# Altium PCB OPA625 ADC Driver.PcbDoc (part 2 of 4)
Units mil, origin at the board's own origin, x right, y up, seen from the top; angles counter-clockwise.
Board outline 4590 x 3930 mil, 4 copper layers (Layer 1 - Top Layer, Layer 2 - GND, Layer 3 - PWR, Layer 4 - Bottom Layer), stack 59.034 mil thick; 428 components, 236 nets, 1203 pads, 546 vias.
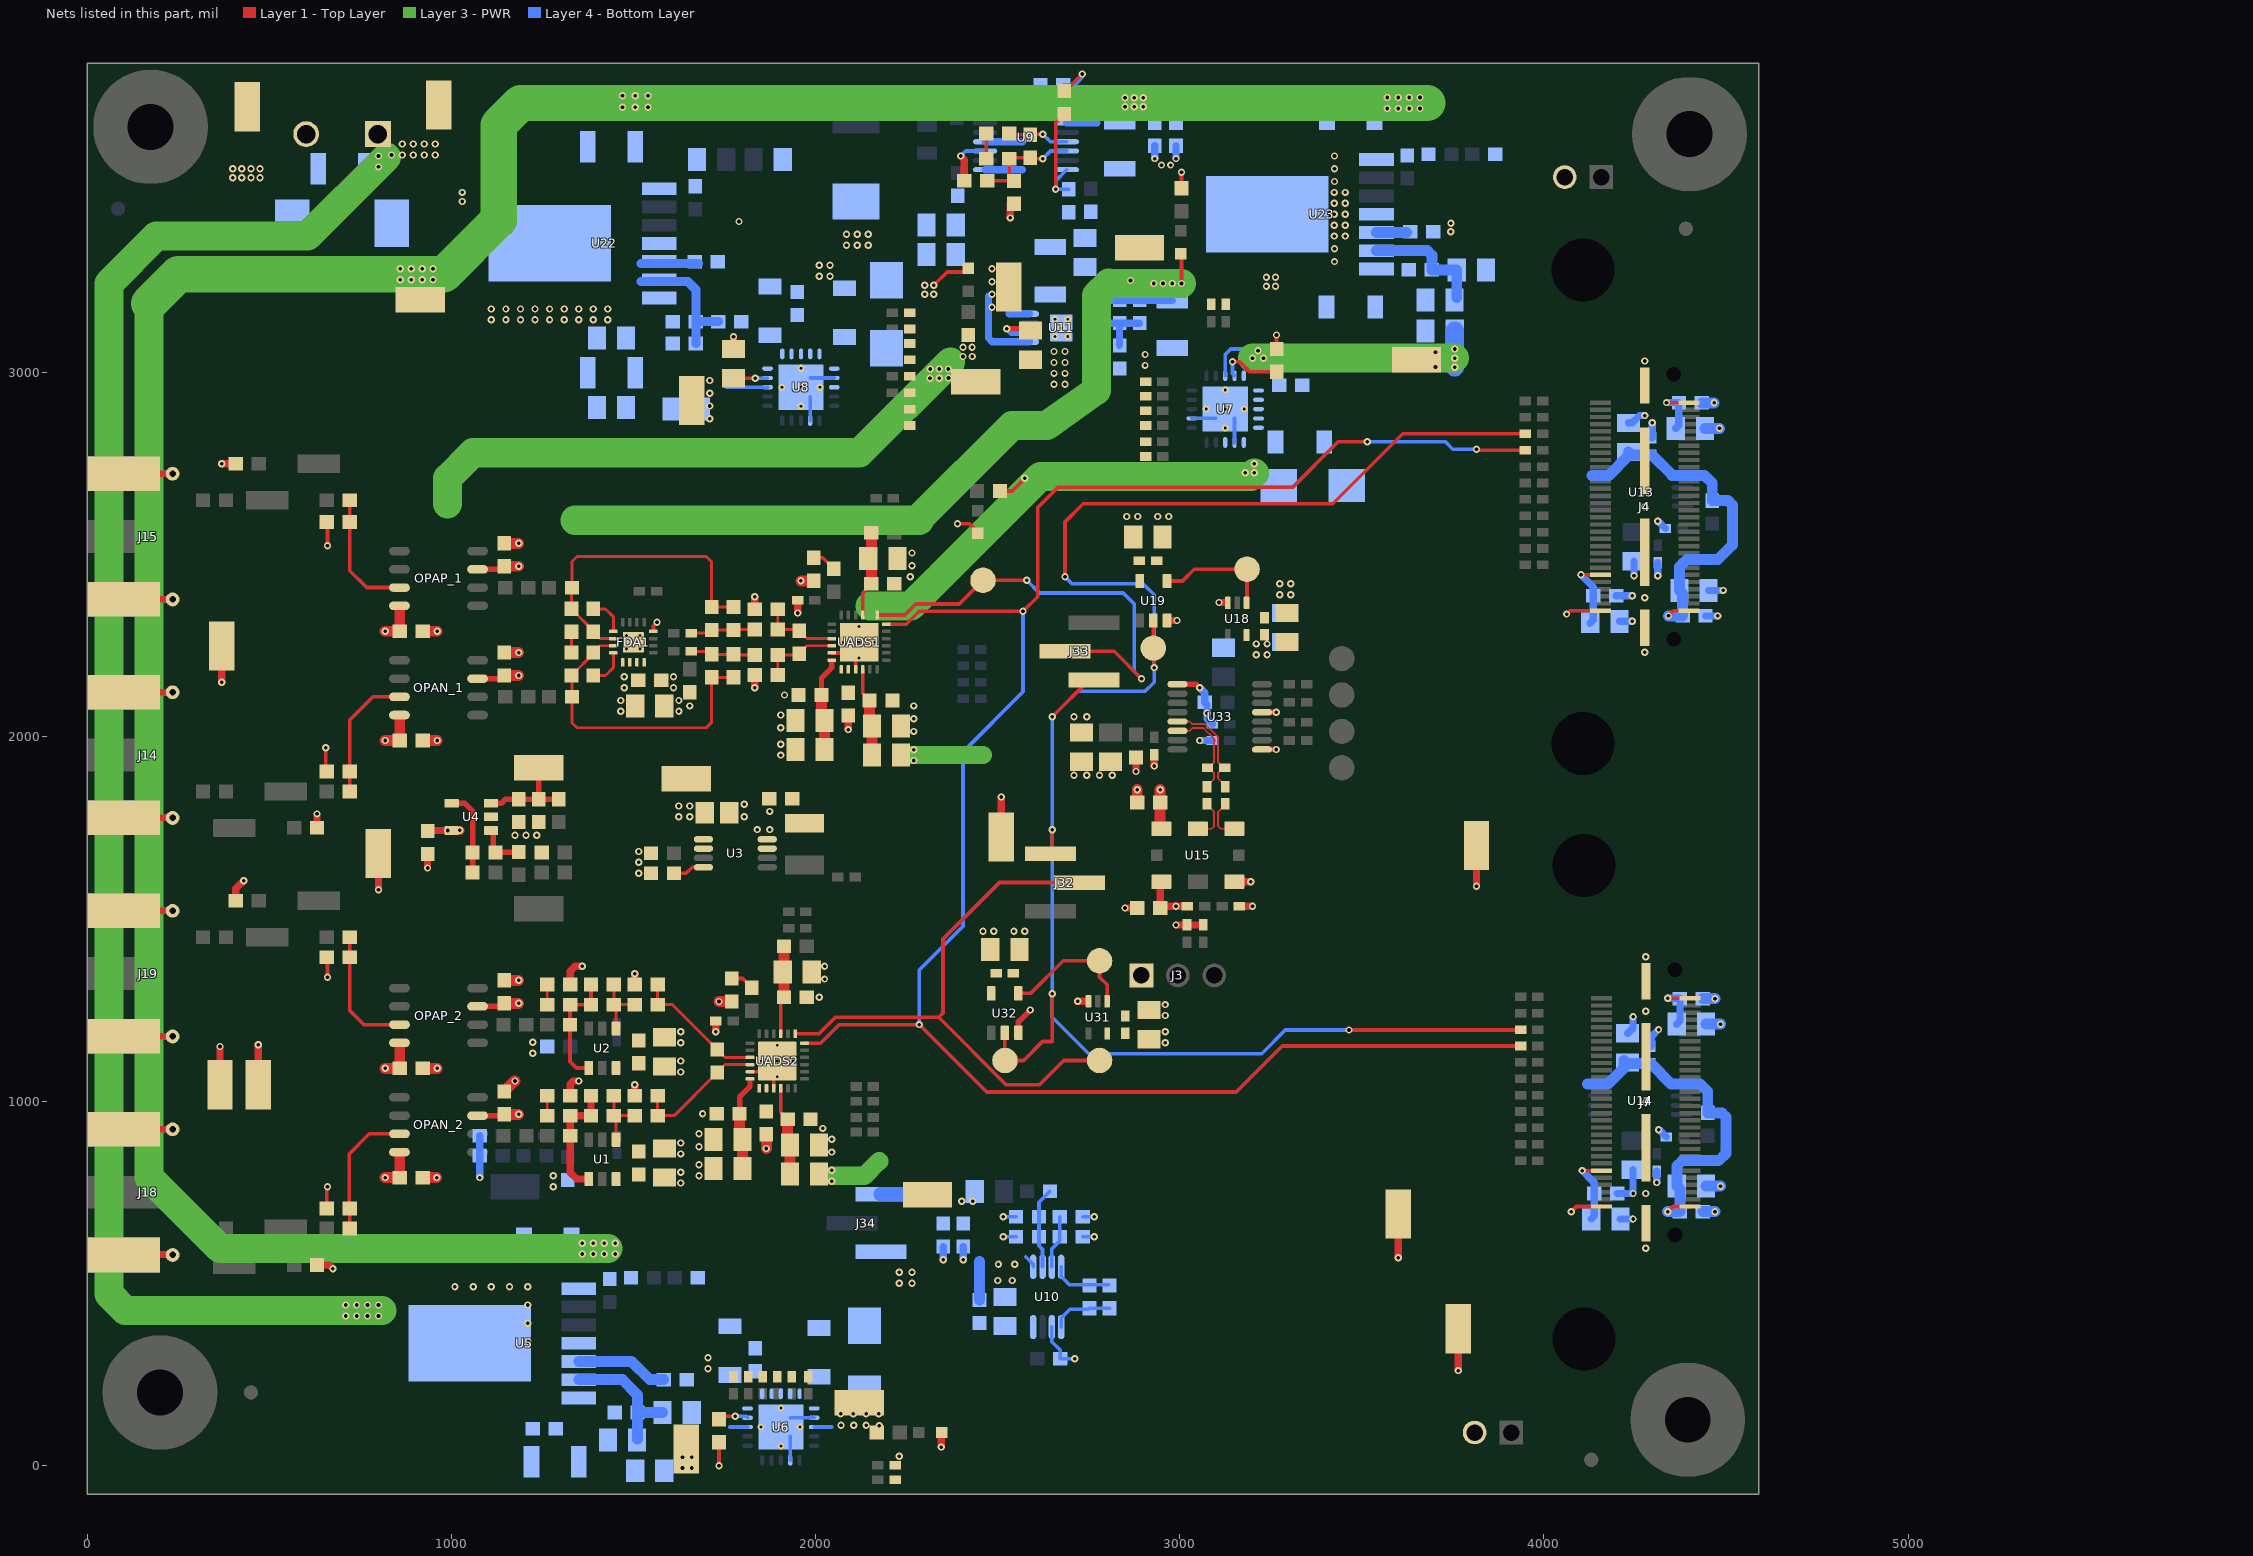
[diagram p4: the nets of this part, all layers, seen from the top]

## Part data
24Vin GNDin TP3 TP8 TP11 TP17 TP25 TP26 Tp27 TP28 TP29 TP30 TP_3P8V TP_5P5V TP_18P5V TPAGND1 TPAGND2 TPAGND3 TPAGND4 TPGND1 TPGND2 TPGND3 TPGND4: "Test Point, Miniature, SMT"
C1 C43 C47 C354 Cin Cin2 Cin3 Cout2: "CAP, CERM, 10 µF, 50 V, +/- 10%, X7R, 1210"
C3: "CAP, CERM, 10uF, 10V, +/-10%, X7R, 0805"
C4: "CAP, CERM, 1uF, 10V, +/-10%, X7R, 0603"
C5: "CAP, CERM, 47 µF, 10 V, +/- 10%, X7R, 1210"
C9 C12 C13 C16 C17 C20 Cout4: "CAP, CERM, 47 µF, 25 V, +/- 20%, X5R, 1206_190"
C10: "CAP, CERM, 1000 pF, 100 V, +/- 10%, X7R, AEC-Q200 Grade 1, 0603"
C11 C42 C45 Cout3: "CAP, CERM, 1 µF, 100 V, +/- 10%, X7S, 0805"
C14 C18: "CAP, CERM, 1000 pF, 50 V, +/- 1%, C0G/NP0, 0603"
C15 C19 C318 C319 C321 C339 C348 Cout6: "CAP, CERM, 1 µF, 25 V, +/- 10%, X7R, 0603"
C21 C22 C57 C58 C59 C60 C261 C262 C271 C272 C284 C287 C288 C289 C290 C291 C304 C305 C306 C307 C308 C338 C343 C345 C347: "CAP, CERM, 10 µF, 10 V, +/- 10%, X7R, 0805"
C23 C24 C33: "CAP, CERM, 10 µF, 10 V, +/- 20%, X5R, 0603"
C25: "CAP, CERM, 0.47 µF, 25 V, +/- 10%, X7R, 0603"
C26 C28: "CAP, CERM, 22 µF, 6.3 V, +/- 20%, X5R, 0603"
C27: "CAP, CERM, 0.1 µF, 16 V, +/- 10%, X5R, 0603"
C29: "CAP, CERM, 4.7 µF, 10 V, +/- 20%, X5R, 0603"
C30: "CAP, CERM, 0.22 µF, 10 V, +/- 10%, X5R, 0603"
C31: "CAP, CERM, 0.22 µF, 50 V, +/- 10%, X7R, AEC-Q200 Grade 1, 0603"
C32 C35: "CAP, CERM, 0.1 µF, 50 V, +/- 10%, X7R, 0603"
C34: "CAP, CERM, 0.033 µF, 50 V, +/- 10%, X7R, 0603"
C37: "CAP, CERM, 910 pF, 50 V, +/- 5%, C0G/NP0, 0603"
C38: "CAP, CERM, 10 pF, 50 V, +/- 5%, C0G/NP0, AEC-Q200 Grade 1, 0603"
C39: "CAP, CERM, 150 pF, 50 V, +/- 5%, C0G/NP0, 0603"
C40: "CAP, CERM, 0.022 µF, 50 V, +/- 10%, X7R, 0603"
C41: "CAP, CERM, 22 µF, 35 V, +/- 20%, X5R, 0805"
C46: "CAP, CERM, 0.01 µF, 50 V, +/- 10%, X7R, AEC-Q200 Grade 1, 0603"
C53 C54 C55 C56 C94 C95 C340 C344 C346 C349 C350: "CAP, CERM, 0.1 µF, 16 V, +/- 10%, X7R, 0402"
C61 C84 C85 C91 C92 C93 C108 C112 C116 C120 C121 C122 C259 C260 C266 C267 C268 C269 C316 C317 C320: "CAP, CERM, 0.1 µF, 25 V, +/- 5%, X7R, 0603"
C62: "CAP, CERM, 10 µF, 10 V, +/- 10%, X7T, 0603"
C63 C64: "CAP, CERM, 0.1 µF, 25 V, +/- 10%, X5R, 0402"
C71 C72 C96 C97 C111 C114: "CAP, CERM, 100 pF, 50 V, +/- 5%, C0G/NP0, 0603"
C79 C80 C81 C82 C104 C105 C106 C107: "CAP, CERM, 0.1 µF, 100 V, +/- 10%, X7R, 0603"
C83: "CAP, CERM, 68 pF, 50 V, +/- 5%, C0G/NP0, 0603"
C86 C87: "CAP, CERM, 27 pF, 50 V, +/- 5%, C0G/NP0, 0603"
C88 C119: "CAP, CERM, 1 µF, 10 V, +/- 10%, X7R, 0603"
C89 C90 C117 C118: "CAP, CERM, 1000 pF, 100 V, +/- 5%, C0G/NP0, 0603"
C109 C115: "CAP, CERM, 1000 pF, 50 V, +/- 5%, C0G/NP0, 0603"
C110 C113: "CAP, CERM, 470 pF, 50 V, +/- 10%, X7R, 0603"
C315 C335: "CAP, CERM, 0.01 µF, 50 V, +/- 5%, C0G/NP0, AEC-Q200 Grade 1, 0603"
C322 C323: "CAP, CERM, 22 µF, 10 V, +/- 20%, X5R, 0603"
C351 C352 C353: "CAP, TA, 4.7 µF, 25 V, +/- 10%, 2 ohm, SMD"
Cff: "CAP, CERM, 0.022 µF, 100 V, +/- 10%, X7R, 0603"
Cff2 Cff3: "CAP, CERM, 0.022uF, 50V, +/-10%, X7R, 0805"
Cout1: "CAP, CERM, 22 µF, 35 V, +/- 20%, JB, 0805"
Cout5: "CAP, CERM, 100 µF, 6.3 V, +/- 20%, X6S, 1210"
Css: "CAP, CERM, 4700 pF, 100 V, +/- 10%, X7R, AEC-Q200 Grade 1, 0603"
Css2 Css3: "CAP, CERM, 0.01 µF, 6.3 V, +/- 10%, X7R, 0603"
D1: "Diode, Schottky, 200V, 4A, SMC"
D14 D18 D21 D22: "LED, Red, SMD"
FDA1: "Low Power, Precision, 160MHz, Fully Differential Amplifier, RGT0016A"
FID1 FID2 FID3 FID4 FID5 FID6: "Fiducial mark.  There is nothing to buy or mount."
H1 H2 H3 H4: "Machine Screw, Round, #4-40 x 1/4, Nylon, Philips panhead"
H5 H6 H7 H8: "Standoff, Hex, 0.5\"L #4-40 Nylon"
H9 H11 H13 H15: "ROUND STANDOFF M3 STEEL 5MM"
J3: "Header, 2.54 mm, 3x1, Gold, TH"
J4 J7: "Header(Shrouded), 19.7mil, 30x2, Gold, SMT"
J5 J6: "Header, 2.54 mm, 2x1, Gold, TH"
J8: "Terminal Block, 2x1, Brass, TH"
J13 J16 J17 J20: "Header, 2.54 mm, 2x1, Gold, R/A, SMT"
J14 J15 J18 J19: "Connector, End launch SMA, 50 ohm, SMT"
J32 J33 J34: "Header, 2mm, 3x1, Gold, SMT"
L1: "Inductor, Shielded Drum Core, Ferrite, 330 µH, 0.42 A, 1.59 ohm, SMD"
L4 L5 L6 L7 L8 L9 L10 L12 L16 L17 L18 L19: "Ferrite Bead, 600 ohm @ 100MHz, 2A, 0805"
Logo1: library part TI_Logo, "Texas Instrument Corporate Signature"
Logo2: library part Pb-Free
NT1 NT2: "Single point connection between nets."
OPAN_1 OPAN_2 OPAP_1 OPAP_2: "Low-Noise, High-Precision, JFET-Input OPERATIONAL AMPLIFIER, D0008A"
R1 R2 R97 R98 R107 R108 R270 R271: "RES, 1.00 k, 0.1%, 0.1 W, 0603"
R3 R4: "RES, 0.22 ohm, 1%, 0.1W, 0603"
R8 R9 R10 R11 R12 R13 R14 R15 R17 R18 R19 R20 R24 R25 R26 R27 R29 R30 R31 R32 R33 R34 R35 R36 R65 R66 R67 R68 R69 R70 R71 R72 R73 R74 R75 R76 R77 R78 R79 R80 R81 R82 R83 R84 R85 R86 R211 R212 R213 R223 R225 R226 R232 R233 R234 R235 R240 R248 R250 R252 R255 R259 R260 R262 R263 R279 R280 R284 R288: "RES, 0, 5%, 0.063 W, 0402"
R21 R219 R220 R221 R222: "RES, 0, 5%, 0.1 W, 0603"
R22: "RES, 4.70, 0.5%, 0.1 W, 0603"
R40: "RES, 215 k, 0.1%, 0.1 W, 0603"
R41: "RES, 23.2 k, 0.1%, 0.1 W, 0603"
R42: "RES, 1.65 k, 0.1%, 0.1 W, 0603"
R43: "RES, 30.9 k, 0.1%, 0.1 W, 0603"
R44: "RES, 2.15 k, 0.1%, 0.1 W, 0603"
R45: "RES, 52.3 k, 0.1%, 0.1 W, 0603"
R46: "RES, 330, 5%, 0.1 W, 0603"
R47: "RES, 18.0 k, 0.1%, 0.1 W, 0603"
R50 R216: "RES, 20.0 k, 0.1%, 0.1 W, 0603"
R64 R87: "RES, 10.0 k, 1%, 0.1 W, 0603"
R88 R89 R90 R91: "RES, 4.7 k, 5%, 0.063 W, 0402"
R92: "RES, 100, 5%, 0.063 W, 0402"
R95 R256 R257 R278: "RES, 33, 5%, 0.063 W, 0402"
R99: "RES, 249, 1%, 0.1 W, 0603"
R100 R101 R114 R116: "RES, 499, 1%, 0.1 W, 0603"
R103 R104 R115 R117: "RES, 10.0, 0.1%, 0.1 W, 0603"
R110 R111 RDN1 RDN2 RDN3 RDN4 RDP1 RDP2 RDP3 RDP4: "RES, 2.00 k, 0.1%, 0.1 W, 0603"
R112 R113: "RES, 30.0, 1%, 0.1 W, 0603"
R214 R215: "RES, 499, 0.1%, 0.1 W, 0603"
R217 R218 R246 R247: "RES, 49.9 k, 0.1%, 0.1 W, 0603"
R258 R261: "RES, 10.0 k, 0.1%, 0.1 W, 0603"
R268 R269: "RES, 1.00, 1%, 0.1 W, 0603"
Renb: "RES, 20.5 k, 1%, 0.125 W, 0805"
Renb2 Renb3: "RES, 3.57 k, 0.1%, 0.1 W, 0603"
Rent: "RES, 118k ohm, 0.1%, 0.125W, 0805"
Rent2 Rent3: "RES, 68.1 k, 0.1%, 0.1 W, 0603"
Rfbb: "RES, 1.50 k, 0.1%, 0.1 W, 0603"
Rfbb3 Rfbb5: "RES, 1.07 k, 0.1%, 0.125 W, 0805"
Rfbt: "RES, 34.0 k, 0.1%, 0.1 W, 0603"
Rfbt2: "RES, 6.34 k, 0.1%, 0.063 W, 0603"
Rfbt3: "RES, 4.02 k, 0.1%, 0.1 W, 0603"
Ron: "RES, 383 k, 0.1%, 0.1 W, 0603"
Ron2: "RES, 113 k, 0.1%, 0.1 W, 0603"
Ron3: "RES, 78.7 k, 0.1%, 0.1 W, 0603"
TP1 TP2 TP4 TP7 TP16 TP31 TP32 TP33 TP34 TP35: library part PogoPad, "Pad for Pogo Pin Connector"
U1 U2: "High Bandwidth, High Precision, Low Noise and Distortion Amplifier with Ultra-Fast Transition time Low Power mode, DBV0006A"
U3: "High-Precision Voltage Reference with Integrated High-Bandwidth Buffer, DGK0008A"
U4: "Precision, Low Noise, Low Iq Operational Amplifier, 2.2 to 5.5 V, -40 to 125 degC, 5-pin SOT23 (DBV0005A), Green (RoHS & no Sb/Br)"
U5: "2A SIMPLE SWITCHER® Power Module with 42V Maximum Input, 7 pin TO-PMOD"
U6 U7 U8: "36-V, 1-A, 4.17-µVRMS, RF LDO Voltage Regulator, RGW0020A"
U9: "SIMPLE SWITCHER® 75V, 0.5A Step-Down Switching Regulator, 16-pin TSSOP"
U10: "Low Noise Negative Bias Generator, 8-pin Mini SOIC, Pb-Free"
U11: "Single Output High PSRR LDO, 200 mA, Adjustable -1.18 to -33 V Output, -3 to -36 V Input, with Ultra-Low Noise, 8-pin MSOP (DGN), -55 to 125 degC, Green (RoHS & no Sb/Br)"
U13 U14: "I2C BUS EEPROM (2-Wire), TSSOP-B8"
U15: "Ultra-Low Jitter Programmable Oscillator with Internal EEPROM, SIA0008B"
U18 U31: "LOW-POWER SINGLE POSITIVE-EDGE-TRIGGERED D-TYPE FLIP-FLOP, DCK0005A"
U19 U32: "SINGLE SCHMITT-TRIGGER INVERTER GATE, DBV0005A"
U22: "1A SIMPLE SWITCHER® Power Module with 42V Maximum Input, 7 pin TO-PMOD"
U23: "3A SIMPLE SWITCHER® Power Module with 42V Maximum Input Voltage, 7-pin TO-PMOD, Pb-Free"
U33: "Low Skew, 1-to-4 Multiplexed Differential/LVCMOS-to-LVCMOS/TTL Fanout Buffer, PW0016A"
UADS1 UADS2: "18-Bit, 1-MSPS SAR ADC with Integrated Reference Buffer, LDO, and Enhanced Serial Interface, RGE0024H"
ZZ2 ZZ3 ZZ4: library part AssemblyNote

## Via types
v1: diameter 20, hole 10, Layer 1 - Top Layer to Layer 4 - Bottom Layer, tented both sides, 512 vias
v2: diameter 19.68, hole 7.87, Layer 1 - Top Layer to Layer 4 - Bottom Layer, tented both sides, 34 vias

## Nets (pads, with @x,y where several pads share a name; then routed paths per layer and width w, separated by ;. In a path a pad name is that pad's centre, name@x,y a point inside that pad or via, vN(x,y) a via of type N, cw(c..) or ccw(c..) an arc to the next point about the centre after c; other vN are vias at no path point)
3.3V: C20.1 C61.1 C62.1 C94.2 C95.2 C290.1 C291.2 C338.1 C343.1 C344.2 C345.2 C346.2 C347.1 C353.1 L4.2 L7.1 L9.1 L10.2 L12.2 R46.2 R88.2 R89.2 R91.1 TP11.1 U6.1 U6.3 U6.20 U15.1@2950,1602.17 U15.6@2950,1747.83 U18.5 U19.5 U31.5 U32.5 | length 719.3
  Layer 1 - Top Layer w20: U15.1@2946.5,1598.66 C62.1@2946.5,1530 2951.5,1535 v1(2990,1535) R91.1@3021.38,1535 ; v1(2990,1483.62) R88.2@3020,1483.62 R89.2@3065,1483.62
  Layer 1 - Top Layer w30: v1(2946.5,1855) C61.1@2946.5,1820 2946.5,1751.34 U15.6@2950,1747.83
  Layer 3 - PWR w50: 2045,795 2135,795 2175,835 ; 2265,1950 2460,1950
  Layer 4 - Bottom Layer w10: U6.3@1996.54,105 2045,105
  other v1: 2175,108.7 2070,110 2105,110 2138.98,110 2068.93,141.07 2103.93,141.07 2138.93,141.07 2173.93,141.07 2500.27,507.23 2540.27,507.23 2044.45,780 2045,810 2960.21,1160 2960.21,1190 2459.83,1466.55 2489.83,1466.55 2710,1895 2745,1895 2780,1895 2815,1895 2270,1935 2270,1965 3210,2225.3 3240,2225.3 3210,2255.3 3240,2255.3 2855,2605 2885,2605
3.8V: C17.1 C18.1 L19.2 TP_3P8V.1 U6.13 U6.15 U6.16 | length 48.5
  Layer 4 - Bottom Layer w10: 1765,105 U6.13@1813.46,105
  other v1: 1635,-7.5 1660.49,-7.5 1635,22.5 1660.49,22.5
5.5V: C13.1 C14.1 L18.2 TP_5P5V.1 U7.13 U7.15 U7.16 | length 774.7
  Layer 3 - PWR w80: v1(3200,3040) v1(3230,3040) v1(3755,3040)
  Layer 4 - Bottom Layer w10: U7.13@3125,2991.54 3125,3050 3140,3065 3180,3065
  Layer 4 - Bottom Layer w50: v1(3755,3015) L18.2@3755,3115
  other v1: 3702.5,3015.76 3702.5,3056.11 3215,3060.04 3755,3065
5V: C3.2 C16.1 C85.1 C112.2 C116.2 C284.1 C304.1 C305.1 C320.2 C352.1 FDA1.5 FDA1.6 FDA1.7 FDA1.8 FDA1.12 L6.1 L8.1 R47.2 TP8.1 U1.6 U2.6 U3.1 U3.2 U4.5 U7.1 U7.3 U7.20 | length 1396.8
  Layer 1 - Top Layer w10: U4.5@1000.87,1742.86 U4.5@1001.34,1743.33 ; FDA1.12@1555.12,2291 1555.12,2305.12 v1(1565,2315) ; R47.2@2506.5,2675 2540,2675 v1(2575,2710)
  Layer 1 - Top Layer w20: C320.2@935,1741.5 936.36,1742.86 v1(990,1742.86)
  Layer 1 - Top Layer w25: U4.5@1001.34,1743.33 v1(1023.52,1743.33)
  Layer 3 - PWR w10: 2335,2432.5 2335,2433.28 2346.72,2445 2347.5,2445
  Layer 3 - PWR w80: 2149.53,2359.53 2262.03,2359.53 2335,2432.5 ; 2347.5,2445 2617.5,2715 3195,2715 v1(3205,2725)
  other v1: 1630,775 1680,795 1630,805 1680,825 1630,1080 1630,1110 1624.79,1780.41 1654.79,1780.41 1624.79,1810.41 1654.79,1810.41 1905,1950 1905,1980 1465,2070 1465,2100 1475,2135 1475,2165 3180,2725 3205,2750
18.5V: Cff.1 Cout1.1 Cout2.1 Cout3.1 L16.2 Rfbt.2 U22.7
+18V: C12.1 C79.2 C81.2 C104.2 C106.2 C351.1 OPAN_1.7 OPAN_2.7 OPAP_1.7 OPAP_2.7 R247.2 TP3.1 U8.1 U8.3 U8.20 | length 2043.6
  Layer 1 - Top Layer w15: OPAN_2.7@1072.28,960 1141.5,960 C104.2@1145,963.5 ; OPAP_2.7@1072.28,1260 1141.5,1260 C106.2@1145,1263.5 ; OPAN_1.7@1072.28,2160 1136.5,2160 C81.2@1145,2168.5 ; OPAP_1.7@1072.28,2460 1136.5,2460 C79.2@1145,2468.5
  Layer 1 - Top Layer w30: C104.2@1145,963.5 v1(1185,963.5) ; C106.2@1145,1268.5 v1(1185,1268.5) ; C81.2@1145,2168.5 v1(1185,2168.5) ; C79.2@1145,2468.5 v1(1185,2468.5)
  Layer 3 - PWR w80: 990,2640 990,2710 1060,2780 1485,2780 2120.93,2780 2370.46,3029.54
  other v1: 2314.51,2985 2340,2985 2365.39,2985.49 2315,3010 2340,3010 2365,3010 2405,3044.51 2430.49,3044.51 2405,3070 2430,3070
+24VDC: C31.1 C32.1 C43.1 Cin2.1 Cin3.1 Cin.1 D1.1 Rent2.2 Rent3.2 Rent.2 Ron2.2 Ron3.2 Ron.2 TP17.1 U5.1 U9.3 U22.1 U23.1 | length 7702.9
  Layer 3 - PWR w80: 170,3180 170,790 365,595 1215,595 1430,595
  Layer 3 - PWR w100: 170,3190 250,3270 980,3270 1130,3420 1130,3680 1190,3740 3680.04,3740.49
  Layer 4 - Bottom Layer w20: U9.3@2690.07,3685.28 2772.07,3685.28
  other v1: 1360,580 1390,580 1420,580 1450,580 1360,610 1390,610 1420,610 1450,610 860,3255 890,3255 920,3255 950,3255 860,3285 890,3285 920,3285 950,3285 3570,3725.49 3600,3725.49 3630,3725.49 3660,3725.49 1470,3728.88 1505,3728.88 1540,3728.88 2850,3730 2875,3730 2900,3730 2850,3755 2875,3755 2900,3755 3570,3755.49 3600,3755.49 3630,3755.49 3660,3755.49 1470,3760 1505,3760 1540,3760
+24VDC_IN: 24Vin.1 C1.1 D1.2 J8.2
  other v1: 400,3535 425,3535 450,3535 475,3535 400,3560 425,3560 450,3560 475,3560
-0.2V: C23.1 C24.1 J34.3 L5.1 Tp27.1 | length 125.8
  Layer 4 - Bottom Layer w40: J34.3@2179.96,743.74 2305.74,743.74
  other v1: 2401.45,724.94 2431.45,724.94
-18.5V: C354.1 L17.1 TP25.1 U11.5 U11.8 | length 287.6
  Layer 4 - Bottom Layer w20: 2475,3210 2475,3095 2485.33,3084.67 U11.5@2587.4,3084.67 ; 2531.44,3161.44 U11.8@2587.4,3161.44
  other v1: 2484.51,3180 2484.51,3215 2484.51,3250 2484.51,3285
-18V: C46.1 C47.1 C80.2 C82.2 C105.2 C107.2 D21.1 OPAN_1.4 OPAN_2.4 OPAP_1.4 OPAP_2.4 R43.2 TP26.1 U11.1 | length 2800.9
  Layer 1 - Top Layer w10: v1(3005,3245) D21.1@3005,3325.06
  Layer 1 - Top Layer w30: v1(818.5,790) C105.2@858.5,790 OPAN_2.4@858.5,855 ; v1(818.5,1090) C107.2@858.5,1090 OPAP_2.4@858.5,1155 ; v1(818.5,1990) C82.2@858.5,1990 OPAN_1.4@858.5,2055 ; v1(818.5,2290) C80.2@858.5,2290 OPAP_1.4@858.5,2355
  Layer 3 - PWR w80: 1340,2595 2285,2595 ; 2290,2605 2540,2855 2635,2855 2771.84,2951.84 2771.84,3211.84 2805.4,3245.4 2864.98,3245.28 2928.53,3245.15 2954.02,3245.1 2979.51,3245.05 v1(3005,3245)
  Layer 4 - Bottom Layer w20: U11.1@2762.6,3161.44 2799.17,3198.01 C47.1@2980,3198.01
  other v1: 2928.53,3245 2954.02,3245 2979.51,3245 2865,3253.05
AGND: C3.1 C4.2 C71.1 C72.1 C79.1 C80.1 C81.1 C82.1 C84.2 C85.2 C88.1 C89.2 C90.2 C91.1 C92.2 C93.2 C96.1 C97.1 C104.1 C105.1 C106.1 C107.1 C108.2 C109.2 C112.1 C115.2 C116.1 C117.2 C118.2 C119.2 C120.1 C121.2 C122.2 C284.2 C287.2 C288.2 C289.2 C304.2 C305.2 C306.2 C307.2 C308.2 C318.2 C320.1 C321.2 FDA1.17 J14.2 J14.3 J14.4 J14.5 J15.2 J15.3 J15.4 J15.5 J18.2 J18.3 J18.4 J18.5 J19.2 J19.3 J19.4 J19.5 NT1.1 NT2.1 R1.2 R2.2 R3.1 R4.2 R111.1 R112.1 R113.1 R217.1 R268.1 R269.1 R270.2 R271.2 R284.1 R288.1 TPAGND1.1 TPAGND2.1 TPAGND3.1 TPAGND4.1 U3.7 U3.8 U4.2 UADS1.11 UADS1.15 UADS1.25 UADS2.11 UADS2.15 UADS2.25 | length 2052.7
  Layer 1 - Top Layer w10: C71.1@655,1908.5 v1(655,1970) ; C96.1@658.5,705 v1@658.5,763.5 ; v1(660,1340) C97.1@660,1393.5 ; v1(660,2525) C72.1@660,2588.5 ; UADS2.11@1820.2,1080.47 UADS2.25@1865.47,1080.47 ; UADS2.15@1885.16,1035.2 UADS2.25@1885.16,1100.16 ; UADS1.11@2045.2,2230.47 2090.47,2230.47 UADS1.25@2110.16,2250.16 ; UADS1.15@2110.16,2185.2 UADS1.25@2110.16,2250.16 ; v2(2120,2260) UADS1.25@2110.16,2250.16
  Layer 1 - Top Layer w20: TPAGND2.1@365,1045 v1(365,1150) ; v1(370,2150) TPAGND1.1@370,2250 ; v1(370,2750) R271.2@408.5,2750 ; R2.2@408.5,1550 408.5,1583.5 v1(430,1605) ; TPAGND4.1@470,1045 v1(470,1155) ; R1.2@631.5,550 665,550 v1(675,540) ; R270.2@631.5,1750 v1(631.5,1788.5) ; v1(800,1580) TPAGND3.1@800,1680 ; v1(935,1640) C320.1@935,1678.5 ; R113.1@1326.5,1015 1326.5,1046.5 1335,1055 v1(1350,1055) ; R112.1@1326.5,1320 1326.5,1356.5 1340,1370 v1(1360,1370) ; C118.2@1503.5,1015 v1(1503.5,1045) ; C117.2@1503.5,1320 v1(1503.5,1350) ; v1(1726.38,1190) R288.1@1726.38,1220 ; v1(1833.5,2135) C89.2@1833.5,2170 ; C90.2@1833.5,2350 v1(1833.5,2385) ; v1(1951.38,2340) R284.1@1951.38,2375 ; v1(2090,2020) C88.1@2090,2058.5
  Layer 1 - Top Layer w30: C105.1@921.5,790 v1(960,790) ; C107.1@921.5,1090 v1(961.5,1090) ; C82.1@921.49,1990 v1(961.49,1990) ; C80.1@921.5,2290 v1(961.5,2290) ; C104.1@1145,1026.5 1173.5,1055 v1(1175,1055) ; C106.1@1145,1331.5 v1(1185,1331.5) ; C81.1@1145,2231.5 v1(1185,2231.5) ; C79.1@1145,2531.5 v1(1185,2531.5) ; v1(1735,1273.5) R269.1@1770,1273.5 ; v1(1865,870) C119.2@1865,908.5 ; v1(1960,2428.5) R268.1@1995,2428.5
  Layer 4 - Bottom Layer w20: v1(1078.5,790) R111.1@1078.5,850 C108.2@1078.5,905
  other v1: 660,765 1280,765 1280,795 1630,855 2044.45,860 1680,875 1630,885 2044.45,895 1680,910 2020,925 1690,965 1223.5,1131.5 1630,1160 1223.5,1161.5 1630,1190 2010,1285 2025,1335 2025,1370 1514.79,1625.41 1514.79,1655.41 1514.79,1685.41 1175,1730.26 1205,1730.26 1235,1730.26 1839.79,1745.41 1874.79,1745.41 1804.79,1780.41 1874.79,1795.41 1804.79,1815.41 2270,2015 1905,2025 2270,2050 1905,2060 1625,2070 1655,2085 2270,2085 1625,2100 1915,2115 1610,2135 1610,2165 2260,2440 2265,2470 2265,2505
  other v2: 1895,1066.69 1851.69,1110 1895,1110 1938.31,1110 1895,1153.31 2120,2216.69 1481.3,2241.3 1518.7,2241.3 2076.69,2260 2163.31,2260 1481.3,2278.7 1518.7,2278.7 2120,2303.31
BCLK0_N: C64.1 U15.5@3050,1747.83 | length 116.9
  Layer 1 - Top Layer w5: U15.5@3050,1747.83 3087.33,1747.83 3094.5,1755 3094.5,1794.51 3075,1814.01 C64.1@3075,1816.38
BCLK0_P: C63.1 U15.4@3150,1747.83 | length 116.9
  Layer 1 - Top Layer w5: C63.1@3125,1816.38 3125,1814 3105.5,1794.5 3105.5,1755 3112.67,1747.83 U15.4@3150,1747.83
BCLK1_N: C64.2 R92.1 U33.6 | length 271.2
  Layer 1 - Top Layer w5: U33.6@2993.86,2016.61 3027.62,2016.61 3035,2024 3065.44,2024 3094.5,1994.94 3094.5,1930.5 R92.1@3079,1915 ; C64.2@3075,1863.62 3075,1866 3094.5,1885.5 3094.5,1900.51 3080,1915 R92.1@3079,1915 ; R92.1@3076.38,1915 R92.1@3079,1915
BCLK1_P: C63.2 R92.2 U33.5 | length 287.9
  Layer 1 - Top Layer w5: U33.5@2993.86,2042.2 3027.8,2042.2 3035,2035 3070,2035 3105.5,1999.5 3105.5,1930.5 3121,1915 R92.2@3123.63,1915 ; R92.2@3119,1915 3105.5,1901.5 3105.5,1885.51 3125,1866 C63.2@3125,1863.63
CONVST: J32.3 J33.3 R67.1 R78.1 TP7.1 TP35.1 U19.2 U32.2 | length 5224.2
  Layer 1 - Top Layer w10: TP35.1@2519.83,1112 U32.2@2519.83,1187.4 ; TP35.1@2520.3,1111.53 2571.53,1111.53 2623.62,1163.62 2650.21,1163.62 v1(2650.21,1294.79) ; J32.3@2650,1683.7 v1(2650,1745) ; v1(2650.21,2055.21) 2751.26,2156.26 J33.3@2764.96,2156.26 ; v1(2685,2440) 2685,2590 2735,2640 3420,2640 3612.19,2832.19 R67.1@3949.45,2832.19 ; U19.2@2927.81,2319.66 TP7.1@2927.81,2243.8 2930,2241.6 v1(2930,2190.3) ; v1(3465,1195) R78.1@3935.05,1195
  Layer 4 - Bottom Layer w10: v1(2685,2440) 2705,2420 2900,2420 2930,2390 v1(2930,2190.3) 2930,2150 2905,2125 2720,2125 v1(2650.21,2055.21) 2650,2055 v1(2650,1745) 2650,1295 v1(2650.21,1294.79) 2650.21,1230.21 2750.43,1130 3225,1130 3290,1195 v1(3465,1195)
CONVST_TO_DIF_ADC: J33.2 TP1.1 UADS1.1 | length 1226.5
  Layer 1 - Top Layer w10: UADS1.1@2169.21,2334.8 2244.8,2334.8 2275,2365 2395,2365 TP1.1@2460,2430 v1(2580,2430) ; J33.2@2685.04,2235 2820,2235 v1(2895,2160)
  Layer 4 - Bottom Layer w10: v1(2580,2430) 2615,2395 2845,2395 2875,2365 2875,2180 v1(2895,2160)
CONVST_TO_SE_ADC: J32.2 TP4.1 UADS2.1 | length 1617.8
  Layer 1 - Top Layer w10: UADS2.1@1944.21,1184.8 2009.8,1184.8 2055,1230 2338.19,1230 ; J32.2@2724.96,1600 2505,1600 2350,1445 2350,1241.81 2338.19,1230 ; TP4.1@2780,1111.53 2681.53,1111.53 2615,1045 2523.19,1045 2338.19,1230
CONVSTN_DIF: TP2.1 U18.1 U19.4 | length 326.1
  Layer 1 - Top Layer w10: U19.4@2965.21,2427.93 3007.64,2427.93 3040,2460.3 TP2.1@3185,2460.3 3185,2369.69 U18.1@3183.4,2368.09
CONVSTN_SE: TP34.1 U31.1 U32.4 | length 379.1
  Layer 1 - Top Layer w10: U32.4@2557.23,1295.67 2590.67,1295.67 2680,1385 TP34.1@2780,1385 2780,1340 2800.8,1319.2 U31.1@2800.8,1274.29
CSN: R68.1 R79.1 UADS1.24 UADS2.24 | length 5484.7
  Layer 1 - Top Layer w10: UADS2.24@1969.8,1159.21 2014.21,1159.21 2065,1210 v1(2285,1210) 2470,1025 3155,1025 3281.32,1151.32 R79.1@3936.37,1151.32 ; UADS1.24@2194.8,2309.21 2249.21,2309.21 2285,2345 v1(2570,2345) 2610,2385 2610,2630 2665,2685 3310,2685 3435,2810 v1(3515,2810) ; v1(3815,2790) 3817.81,2787.19 R68.1@3949.45,2787.19
  Layer 4 - Bottom Layer w10: v1(2285,1210) 2285,1360 2405,1480 2405,1958.79 2570,2123.79 v1(2570,2345) ; v1(3515,2810) 3730,2810 3750,2790 v1(3815,2790)
EVM_DVDD_0: C22.1 C266.1 J4.50 | length 203.5
  Layer 1 - Top Layer w10: v1(4102.03,2445.08) J4.50@4155.35,2445.08
  Layer 4 - Bottom Layer w20: v1(4102.03,2445.08) 4135.35,2411.76 4135.35,2320.69 C22.1@4126.85,2312.18
EVM_DVDD_1: C21.1 C268.1 J7.50 | length 203.5
  Layer 1 - Top Layer w10: v1(4105.17,809.22) J7.50@4158.5,809.22
  Layer 4 - Bottom Layer w20: v1(4105.17,809.22) 4138.5,775.89 C268.1@4138.5,746.32 4138.5,684.82 C21.1@4129.99,676.32
EVM_ID_PWR_0: C53.2 C58.1 C259.1 C271.1 J4.59 R64.2 U13.1 U13.8 | length 1024.9
  Layer 1 - Top Layer w10: v1(4342.34,2332.19) 4356.74,2346.58 J4.59@4398.35,2346.58
  Layer 4 - Bottom Layer w30: 4132.34,2718.19 4178.34,2718.19 4232.34,2772.19 C271.1@4232.34,2782.19 4240.96,2773.57 C53.2@4297.34,2773.57 4352.34,2718.57 4352.34,2718.19 4441.34,2718.19 4462.34,2697.18 R64.2@4462.34,2648.68 4505.85,2648.68 4517.34,2637.19 4517.34,2527.19 4477.34,2487.19 4392.34,2487.19 4372.34,2467.19 C58.1@4372.34,2402.19 4380.85,2393.68 C259.1@4380.85,2332.19 v1(4342.34,2332.19)
EVM_ID_PWR_1: C55.2 C60.1 C260.1 C272.1 J7.59 R87.2 U14.1 U14.8 | length 995.7
  Layer 1 - Top Layer w10: v1(4339.99,696.32) 4354.39,710.72 J7.59@4401.5,710.72
  Layer 4 - Bottom Layer w30: 4119.99,1047.32 4176,1047.32 4219.99,1091.31 4219.99,1111.32 4228.61,1102.7 4293.61,1102.7 4348.99,1047.32 4428.99,1047.32 4450,1026.32 R87.2@4450,967.82 4488.49,967.82 4499.99,956.32 4499.99,856.32 4479.99,836.32 4379.99,836.32 4365,821.33 C60.1@4365,766.32 4373.5,757.81 C260.1@4373.5,696.32 v1(4339.99,696.32)
EVM_REG_5V5_0: C57.1 C267.1 J4.1 | length 168.8
  Layer 1 - Top Layer w10: v1(4336.85,2917.88) J4.1@4398.35,2917.88
  Layer 4 - Bottom Layer w20: v1(4336.85,2917.88) 4369.67,2917.88 4370.36,2917.2 4370.36,2855.68 C57.1@4361.85,2847.18
EVM_REG_5V5_1: C59.1 C269.1 J7.1 | length 168.8
  Layer 1 - Top Layer w10: v1(4339.99,1282.02) J7.1@4401.5,1282.02
  Layer 4 - Bottom Layer w20: v1(4339.99,1282.02) 4372.82,1282.02 C269.1@4373.5,1281.33 4373.5,1219.82 C59.1@4365,1211.32
FB_3P3V: Cff3.2 Rfbb3.2 Rfbt3.1 U5.6 | length 368.6
  Layer 4 - Bottom Layer w30: U5.6@1350.63,235 1470,235 1511.5,193.5 Rfbt3.1@1511.5,145 ; Cff3.2@1511.5,71.5 Rfbt3.1@1511.5,145 ; Rfbb3.2@1580,145 Rfbt3.1@1511.5,145
FB_5V: Cff2.2 Rfbb5.2 Rfbt2.1 U23.6 | length 342.1
  Layer 4 - Bottom Layer w30: U23.6@3540.39,3335 3679.76,3335 3692.26,3322.5 Rfbt2.1@3692.26,3282.2 Rfbb5.2@3760.76,3282.2 Cff2.2@3760.76,3206
FB_18V: Cff.2 Rfbb.2 Rfbt.1 U22.6 | length 370.3
  Layer 4 - Bottom Layer w25: 1520.63,3250 1650,3250 1671.5,3228.5 Rfbt.1@1671.5,3140 ; Cff.2@1671.5,3080 Rfbt.1@1671.5,3140 ; Rfbb.2@1733.5,3140 Rfbt.1@1671.5,3140
GND: C1.2 C9.2 C10.2 C11.2 C12.2 C13.2 C14.2 C15.1 C16.2 C17.2 C18.2 C19.1 C20.2 C21.2 C22.2 C23.2 C24.2 C25.2 C26.2 C27.2 C28.2 C31.2 C32.2 C33.2 C41.1 C42.1 C45.2 C47.2 C53.1 C54.1 C55.1 C56.1 C57.2 C58.2 C59.2 C60.2 C61.2 C62.2 C94.1 C95.1 C259.2 C260.2 C261.2 C262.2 C266.2 C267.2 C268.2 C269.2 C271.2 C272.2 C290.2 C291.1 C338.2 C339.2 C340.2 C343.2 C344.1 C345.1 C346.1 C347.2 C348.2 C349.2 C350.2 C351.2 C352.2 C353.2 C354.2 Cin2.2 Cin3.2 Cin.2 Cout1.2 Cout2.2 Cout3.2 Cout4.2 Cout5.2 Cout6.2 Css2.2 Css3.2 Css.1 D14.1 D18.1 D22.1 GNDin.1 J3.1 J4.60 J4.MP1 J4.MP2 J4.MP3 J4.MP4 J5.2 J6.2 J7.60 J7.MP1 J7.MP2 J7.MP3 J7.MP4 J8.1 J34.1 L1.2 NT1.2 NT2.2 R8.1 R9.1 R10.1 R11.1 R12.1 R13.1 R14.1 R15.1 R17.1 R18.1 R19.1 R20.1 R21.1 R24.1 R25.1 R26.1 R27.1 R29.1 R30.1 R31.1 R32.1 R33.1 R34.1 R35.1 R36.1 R41.2 R44.1 R90.1 R246.2 R279.1 R280.1 Renb2.1 Renb3.1 Renb.1 Rfbb3.1 Rfbb5.1 Rfbb.1 TPGND1.1 TPGND2.1 TPGND3.1 TPGND4.1 U5.4 U5.8 U6.2 U6.7 U6.17 U6.18 U6.19 U6.21 U7.2 U7.7 U7.17 U7.18 U7.19 U7.21 U8.2 U8.7 U8.17 U8.18 U8.19 U8.21 U9.11 U10.2 U10.5 U11.4 U11.9 U15.3@3150,1602.17 U18.3 U19.3 U22.4 U22.8 U23.4 U23.8 U31.3 U32.3 U33.1 U33.9 U33.13 | length 8108.8
  Layer 1 - Top Layer w10: v1(1735,-1.02) C19.1@1735,57.48 ; v1(2325,3240) 2361.5,3276.5 D22.1@2420,3276.5 ; v1(2390,2585) 2422.89,2585 2445,2562.89 D18.1@2445,2558.5 ; R246.2@3005,3506.5 v1(3005,3550) ; C15.1@3266.02,3065.15 v1(3266.02,3103.66) ; v1(4062.34,2337.19) 4071.74,2346.58 J4.60@4155.35,2346.58 ; v1(4074.99,696.32) 4089.39,710.72 J7.60@4158.5,710.72
  Layer 1 - Top Layer w15: U32.3@2557.23,1187.4 2557.23,1217.23 v1(2590,1250) ; U33.1@2993.86,2144.57 3045.43,2144.57 v1(3055,2135) ; U33.9@3226.14,1965.43 v1(3265,1965.43) ; U33.13@3226.14,2067.8 v1(3265,2067.8)
  Layer 1 - Top Layer w20: C11.2@1775,3065 v1(1775,3099) ; v1(2345,50) D14.1@2345,80 ; v1(2399.25,3594.94) 2408.65,3585.54 R41.2@2408.65,3526.89 ; TPGND2.1@2510,1725 v1(2510,1835) ; v1(2720.21,1274.29) U31.3@2745.21,1274.29 ; v1(2850.01,1530) C62.2@2883.5,1530 ; v1(2880,1905) C339.2@2880,1943.51 ; v1(2930,1920) C340.2@2930,1951.38 ; U19.3@2965.21,2319.66 v1(2992.81,2319.66) ; v1(3107.81,2368.82) U18.3@3127.81,2368.82 ; U15.3@3150,1602.17 v1(3195,1602.17) ; R90.1@3163.62,1535 v1(3200,1535) ; v1(3600,570) TPGND4.1@3600,690 ; v1(3765,260) TPGND1.1@3765,375 ; v1@3814.99,1596.32 TPGND3.1@3814.99,1701.32
  Layer 1 - Top Layer w30: C61.2@2883.5,1820 v1(2883.5,1855)
  Layer 3 - PWR w80: 810,425 105,425 60,470 60,3245 190,3375 605,3375 822.5,3592.5
  Layer 4 - Bottom Layer w10: U6.7@1930.59,13.46 U6.21@1930.59,79.41 ; U6.21@1930.59,130.59 U6.2@1996.54,130.59 ; U8.7@1985.59,2868.46 U8.21@1985.59,2934.41 ; U8.21@1985.59,2985.59 U8.2@2051.54,2985.59 ; v1(2399.25,3594.94) 2412.81,3608.5 U9.11@2465.66,3608.5 ; v1(2515.27,627.23) C25.2@2550.75,627.23 ; v1(2515.27,682.23) C26.2@2550.75,682.23 ; 2577.25,572.23 2597.95,551.53 U10.5@2597.95,544.9 ; U10.2@2649.13,379.55 2649.13,338.89 2671.76,316.26 R21.1@2671.76,292.23 v1(2712.25,292.23) ; C27.2@2733.75,627.23 v1(2765.27,627.23) ; C28.2@2733.75,682.23 v1(2765.27,682.23) ; U7.7@3033.46,2874.41 U7.21@3099.41,2874.41 ; U7.2@3150.59,2808.46 U7.21@3150.59,2874.41
  Layer 4 - Bottom Layer w20: v1(2350.95,564.21) C24.2@2351.02,600.73 ; v1(2405.95,564.21) C23.2@2406.02,600.73 ; v1(2931.46,3587.85) C31.2@2931.46,3623.5 ; v1(2990,3587.85) C32.2@2990,3623.5 ; v1(3055,1990) C350.2@3089.93,1990 ; v1(3055,2135) 3068.5,2121.5 C348.2@3068.5,2095 3075,2088.5 v1(3075,2065) 3075,2049.93 C349.2@3089.93,2035 ; C266.2@4198.84,2387.19 v1(4242.34,2387.19) ; C268.2@4201.49,746.32 v1(4244.99,746.32) C261.2@4244.99,811.32 ; C22.2@4207.34,2317.19 v1(4242.34,2317.19) ; C21.2@4209.99,676.32 v1(4244.99,676.32) ; C272.2@4229.99,1186.32 4244.99,1201.32 v1(4244.99,1231.32) ; C271.2@4232.34,2862.19 4242.35,2862.19 4262.34,2882.18 v1(4276.85,2882.18) ; v1(4247.34,2442.19) C262.2@4247.34,2482.19 ; C55.1@4294.99,1149.94 4294.99,1176.32 v1(4314.99,1196.32) ; C53.1@4297.34,2820.81 v1(4297.34,2862.19) ; v1(4310,776.32) C56.1@4310,807.69 ; v1(4312.34,2442.19) C54.1@4312.34,2478.56 ; v1@4313.72,2592.19 R279.1@4333.72,2572.19 ; v1(4314.99,921.32) 4316.37,921.32 R280.1@4336.37,901.32 ; C259.2@4443.84,2332.19 v1(4477.34,2332.19) ; C58.2@4452.34,2402.19 v1(4492.34,2402.19)
  Layer 4 - Bottom Layer w30: C33.2@2450.2,453.72 2450.2,559.27 ; C267.2@4433.84,2917.19 v1(4467.34,2917.19) ; C260.2@4436.5,696.32 v1(4470,696.32) ; C269.2@4436.5,1281.33 v1(4470,1281.33) ; C57.2@4442.34,2847.19 v1(4482.34,2847.19) ; C60.2@4445,766.32 v1(4485,766.32) ; C59.2@4445,1211.32 v1(4485,1211.31)
  other v1: 2230,25 1705,265 1705,295 1210,340 1210,390 710,410 740,410 770,410 800,410 710,440 740,440 770,440 800,440 1210,440 1010,490 1060,490 1110,490 1160,490 1210,490 2230,500 2265,500 2230,530 2265,530 2502.25,552.23 2547.25,552.23 4280,596.32 4280,746.32 4280,996.32 2960.21,1235 4280,1246.32 2960.21,1265 4280,1396.32 2544.83,1466.55 2574.83,1466.55 3815,1590 2710,2055 2745,2055 4276.85,2232.18 4276.85,2382.18 3275,2390.3 3305,2390.3 3275,2420.3 3305,2420.3 4312.34,2592.19 2940,2605 2970,2605 4276.85,2632.18 2655,2968.05 2685,2968.05 2655,2998.05 2685,2998.05 2905,3020 2655,3028.05 2685,3028.05 4276.85,3032.18 2905,3050 2655,3058.05 2685,3058.05 1110,3145 1150,3145 1190,3145 1230,3145 1270,3145 1310,3145 1350,3145 1390,3145 1430,3145 1110,3175 1150,3175 1190,3175 1230,3175 1270,3175 1310,3175 1350,3175 1390,3175 1430,3175 2300,3215 2325,3215 3238.12,3237.28 3263.12,3237.28 2300,3240 3238.12,3262.28 3263.12,3262.28 2010,3265 2040,3265 2010,3295 2040,3295 3425,3305 3425,3340 2085,3350 2114.98,3350 2145,3350 3424.76,3375 3454.76,3375 2085,3380 2115,3380 2145,3380 3744.65,3387.01 3424.76,3405 3454.76,3405 3744.76,3410 1790,3415 3424.76,3435 3454.76,3435 3424.76,3465 3454.76,3465 1030,3470 1030,3495 3424.76,3495 3454.76,3495 3425,3525 3425,3560 800,3565 2950,3570 2975,3570 800,3595 3425,3595 835.69,3597.89 865.69,3597.89 895.69,3597.89 925.69,3597.89 955.69,3597.89 865.69,3627.89 895.69,3627.89 925.69,3627.89 955.69,3627.89
  other v2: 1905,52.83 1850,105 1905,105 1957.17,105 1905,157.17 3125,2847.83 3072.83,2900 3125,2900 3177.17,2900 1960,2907.83 3125,2952.17 1907.83,2960 1960,2960 2012.17,2960 1960,3012.17 2657.28,3099.43 2692.72,3099.43 2675,3123.05 2657.28,3146.67 2692.72,3146.67
NetC4_1: C4.1 U3.4 | length 87.8
  Layer 1 - Top Layer w10: C4.1@1611.5,1625.41 1644.79,1625.41 1661.4,1642.03 U3.4@1692.4,1642.03
NetC5_2: C5.2 R4.1
NetC9_1: C9.1 C10.1 L16.1 TP_18P5V.1 U8.13 U8.15 U8.16 | length 113.5
  Layer 4 - Bottom Layer w10: 1755,2960 U8.13@1868.46,2960
  other v1: 1710,2873.54 1710,2908.54 1710,2943.54 1710,2978.54
NetC11_1: C11.1 U8.14 | length 92.9
  Layer 1 - Top Layer w10: C11.1@1775,2985 v1(1835,2985)
  Layer 4 - Bottom Layer w10: v1(1835,2985) U8.14@1867.87,2985
NetC15_2: C15.2 U7.14 | length 172.5
  Layer 1 - Top Layer w10: v1(3145,3030) 3165,3030 3192.84,3002.16 C15.2@3266.02,3002.16
  Layer 4 - Bottom Layer w10: v1(3145,3030) 3145,2997.13 U7.14@3150,2992.13
NetC19_2: C19.2 U6.14 | length 71.8
  Layer 1 - Top Layer w10: C19.2@1743.5,135 v1(1780,135)
  Layer 4 - Bottom Layer w10: v1(1780,135) 1809.06,135 U6.14@1813.46,130.59
NetC25_1: C25.1 C26.1 R22.1 U10.6 | length 223.8
  Layer 4 - Bottom Layer w10: U10.6@2623.54,544.9 2623.54,592.74 2613.75,602.53 C25.1@2613.75,627.23 C26.1@2613.75,682.23 2613.75,722.23 R22.1@2643.75,752.23
NetC27_1: C27.1 C28.1 U10.7 | length 146.3
  Layer 4 - Bottom Layer w10: U10.7@2649.13,544.9 2649.13,594.1 2670.75,615.73 C27.1@2670.75,627.23 C28.1@2670.75,682.23
NetC29_1: C29.1 C30.1 U10.1 | length 168.5
  Layer 4 - Bottom Layer w10: U10.1@2674.72,379.55 2674.72,404.69 2698.79,428.76 2750.28,428.76 C29.1@2752.25,430.73 C30.1@2807.25,430.73
NetC29_2: C29.2 C30.2 U10.8 | length 166.5
  Layer 4 - Bottom Layer w10: U10.8@2674.72,544.9 2674.72,518.33 2697.36,495.69 C30.2@2805.28,495.69
NetC33_1: C33.1 L4.1 U10.4
NetC34_2: C34.2 C35.2 C37.2 C41.2 C42.2 C43.2 L17.2 R42.1 R50.1 U9.9 U9.12 | length 245.2
  Layer 1 - Top Layer w20: v1(2535.15,3424.94) R42.1@2535.15,3465.39
  Layer 4 - Bottom Layer w20: U9.9@2465.66,3557.32 2567.43,3557.32 ; U9.12@2465.66,3634.09 2568.64,3634.09
NetC35_1: C35.1 R45.1 U9.1 | length 208.9
  Layer 1 - Top Layer w10: R45.1@2687.06,3781.89 2680.75,3775.57 R45.1@2682.93,3773.39 2684.43,3771.89 2717.54,3805 v1(2732.54,3820)
  Layer 4 - Bottom Layer w10: U9.1@2690.07,3736.46 2690.07,3780.61 C35.1@2680.75,3789.94 2711.2,3789.94 2726.26,3805 2732.54,3811.28 v1(2732.54,3820)
NetC37_1: C37.1 R45.2 U9.8 | length 319.4
  Layer 1 - Top Layer w10: v1(2659.25,3503.39) 2659.25,3684.94 2682.93,3708.62 R45.2@2682.93,3710.39
  Layer 4 - Bottom Layer w10: U9.8@2690.07,3557.32 2659.25,3526.5 v1(2659.25,3503.39) C37.1@2695.15,3503.39
NetC38_1: C38.1 C39.1 R41.1 R42.2 U9.6 | length 293.7
  Layer 1 - Top Layer w10: R41.1@2471.64,3526.89 2533.65,3526.89 2535.15,3528.39 2531.64,3531.89 C39.1@2531.64,3586.89 2535.15,3590.39 C38.1@2590.15,3590.39 2592.88,3587.66 v1(2624.25,3587.66)
  Layer 4 - Bottom Layer w10: v1(2624.25,3587.66) 2645.1,3608.5 U9.6@2690.07,3608.5
NetC38_2: C38.2 R40.1 U9.5 | length 169.2
  Layer 1 - Top Layer w10: R40.1@2531.64,3656.89 2535.15,3653.39 C38.2@2590.15,3653.39 2591.7,3654.94 v1(2624.25,3654.94)
  Layer 4 - Bottom Layer w10: v1(2624.25,3654.94) 2645.1,3634.09 U9.5@2690.07,3634.09
NetC39_2: C39.2 R40.2 | length 70
  Layer 1 - Top Layer w10: C39.2@2468.65,3586.89 R40.2@2468.65,3656.89
NetC40_2: C40.2 U9.16 | length 88.9
  Layer 4 - Bottom Layer w10: C40.2@2387.87,3763.39 2390.8,3763.39 2417.73,3736.46 U9.16@2465.66,3736.46
NetC45_1: C45.1 U11.6 | length 132.9
  Layer 1 - Top Layer w15: v1(2525.21,3120.7) 2584.27,3120.7 C45.1@2589.27,3115.7
  Layer 4 - Bottom Layer w15: v1(2525.21,3120.7) 2538.01,3107.91 U11.6@2586.67,3107.91
NetC46_2: C46.2 R43.1 R44.2 U11.2 | length 188.7
  Layer 4 - Bottom Layer w10: R43.1@2835,3135.85 R43.1@2835,3136.56
  Layer 4 - Bottom Layer w20: U11.2@2762.6,3135.85 R43.1@2835,3135.85 ; R44.2@2835,3074.55 R43.1@2835,3135.85 ; C46.2@2889.29,3135.85 R43.1@2835,3135.85
NetC71_2: C71.2 OPAN_1.3 R97.2 | length 359
  Layer 1 - Top Layer w10: R97.2@721.5,1850 C71.2@721.5,1905 721.5,2046.5 785,2110 OPAN_1.3@857.71,2110
NetC72_2: C72.2 OPAP_1.3 R98.2 | length 349
  Layer 1 - Top Layer w10: R98.2@721.5,2650 C72.2@721.5,2590 721.5,2456.5 767.99,2410 OPAP_1.3@857.72,2410
NetC83_1: C83.1 R99.1 | length 57
  Layer 1 - Top Layer w8: R99.1@1330,2231.5 C83.1@1330,2288.5
NetC83_2: C83.2 C86.2 C317.2 FDA1.2 R101.1 RDN2.2 | length 859.9
  Layer 1 - Top Layer w8: FDA1.2@1444.88,2269.84 1408.66,2269.84 C317.2@1390,2288.5 1390,2291.5 C83.2@1330,2351.5 1330,2408.5 RDN2.2@1331.5,2410 1331.5,2481.5 1345,2495 1700,2495 1715,2480 C86.2@1715,2356.5 R101.1@1775,2356.5
NetC86_1: C86.1 R101.2 R104.1 R212.2 | length 179
  Layer 1 - Top Layer w8: R212.2@1658.62,2285 1706.5,2285 C86.1@1715,2293.5 R101.2@1775,2293.5 1776.5,2295 R104.1@1833.5,2295
NetC87_1: C87.1 R100.2 R103.1 R211.2 | length 179
  Layer 1 - Top Layer w8: R211.2@1658.62,2235 1706.5,2235 C87.1@1715,2226.5 R100.2@1775,2226.5 1776.5,2225 R103.1@1833.5,2225
NetC87_2: C87.2 C316.2 FDA1.3 R99.2 R100.1 RDP2.2 | length 859.9
  Layer 1 - Top Layer w8: FDA1.3@1444.88,2250.16 1408.66,2250.16 C316.2@1390,2231.5 1390,2228.5 R99.2@1330,2168.5 1331.5,2167.01 RDP2.2@1331.5,2110 1331.5,2038.5 1345,2025 1700,2025 1715,2040 C87.2@1715,2163.5 R100.1@1775,2163.5
NetC88_2: C88.2 UADS1.13 UADS1.14
NetC89_1: C89.1 C315.1 R103.2 UADS1.10 | length 209.2
  Layer 1 - Top Layer w8: C89.1@1896.5,2170 R103.2@1896.5,2225 C315.1@1951.5,2225 ; C315.1@1955,2228.5 1976.65,2250.16 UADS1.10@2045.2,2250.16
NetC90_1: C90.1 C315.2 R104.2 UADS1.9 | length 209.2
  Layer 1 - Top Layer w8: C90.1@1896.5,2350 R104.2@1896.5,2295 C315.2@1951.5,2295 ; C315.2@1955,2291.5 1976.65,2269.84 UADS1.9@2045.2,2269.84
NetC91_2: C91.2 C287.1 L8.2 UADS1.12 | length 258.4
  Layer 1 - Top Layer w15: C91.2@2016.5,2115 2016.5,2161.5 2045.2,2190.2 UADS1.12@2045.2,2208
  Layer 1 - Top Layer w30: C91.2@2016.5,2115 2016.5,2053.5 C287.1@2025,2045 L8.2@2025,1965
NetC92_1: C92.1 C288.1 L9.2 UADS1.16 | length 245.6
  Layer 1 - Top Layer w10: UADS1.16@2129.84,2185.2 2129.84,2120.16 2148.5,2101.5 C92.1@2148.5,2100
  Layer 1 - Top Layer w30: C92.1@2148.5,2100 2148.5,2036.5 C288.1@2155,2030 L9.2@2155,1950
NetC93_1: C93.1 C289.1 R258.1 UADS1.3 | length 242
  Layer 1 - Top Layer w10: UADS1.3@2129.84,2334.8 2129.84,2394.84 2153.5,2418.5 C93.1@2153.5,2420
  Layer 1 - Top Layer w30: C93.1@2153.5,2420 2153.5,2481.5 C289.1@2145,2490 2153.5,2498.5 R258.1@2153.5,2560
NetC96_2: C96.2 OPAN_2.3 R107.2 | length 371
  Layer 1 - Top Layer w8: R107.2@721.5,650 723.5,652.01 R107.2@723.5,650
  Layer 1 - Top Layer w10: R107.2@721.5,650 C96.2@721.5,705 720,706.5 720,855 775,910 OPAN_2.3@857.72,910
NetC97_2: C97.2 OPAP_2.3 R108.2 | length 353.7
  Layer 1 - Top Layer w10: R108.2@721.5,1450 C97.2@721.5,1395 721.5,1248.5 760,1210 OPAP_2.3@857.72,1210
NetC110_1: C110.1 R113.2 | length 55
  Layer 1 - Top Layer w8: C110.1@1263.5,960 R113.2@1263.5,1015
NetC110_2: C110.2 C111.2 R114.1 RDP4.2 U1.4 | length 326.9
  Layer 1 - Top Layer w20: U1.4@1377.6,785.87 1344.13,785.87 1326.5,803.5 RDP4.2@1326.5,905 C110.2@1326.5,960 C111.2@1383.5,960 R114.1@1383.5,1015
NetC111_1: C111.1 R114.2 R115.1 U1.1 | length 180.3
  Layer 1 - Top Layer w8: R114.2@1446.5,1015 C111.1@1446.5,960 ; U1.1@1452.4,894.13 1452.4,954.09 C111.1@1446.5,960 ; R115.1@1503.5,960 C111.1@1446.5,960
NetC113_1: C113.1 C114.2 R116.1 RDN4.2 U2.4 | length 327.2
  Layer 1 - Top Layer w10: U2.4@1377.6,1090.87 1344.13,1090.87 1326.18,1108.82 RDN4.2@1326.18,1210 1326.18,1264.68 C113.1@1326.5,1265 C114.2@1383.5,1265 R116.1@1383.5,1320
NetC113_2: C113.2 R112.2 | length 55
  Layer 1 - Top Layer w8: C113.2@1263.5,1265 R112.2@1263.5,1320
NetC114_1: C114.1 R116.2 R117.1 U2.1 | length 180.3
  Layer 1 - Top Layer w8: R116.2@1446.5,1320 C114.1@1446.5,1265 ; U2.1@1452.4,1199.13 1452.4,1259.09 C114.1@1446.5,1265 ; R117.1@1503.5,1265 C114.1@1446.5,1265
NetC117_1: C117.1 C335.2 R117.2 UADS2.9 | length 366.5
  Layer 1 - Top Layer w8: C117.1@1566.5,1320 R117.2@1566.5,1265 1607,1265 C335.2@1728.5,1143.5 ; C335.2@1730,1141.5 1751.65,1119.84 UADS2.9@1820.2,1119.84
NetC118_1: C118.1 C335.1 R115.2 UADS2.10 | length 364.4
  Layer 1 - Top Layer w8: C118.1@1566.5,1015 R115.2@1566.5,960 1612,960 C335.1@1728.5,1076.5 ; C335.1@1730,1078.5 1751.65,1100.16 UADS2.10@1820.2,1100.16
NetC119_1: C119.1 UADS2.13 UADS2.14
NetC120_2: C120.2 C306.1 L6.2 UADS2.12 | length 258.4
  Layer 1 - Top Layer w15: C120.2@1791.5,965 1791.5,1011.5 1820.2,1040.2 UADS2.12@1820.2,1058
  Layer 1 - Top Layer w30: C120.2@1791.5,965 1791.5,903.5 C306.1@1800,895 L6.2@1800,815
NetC121_1: C121.1 C307.1 L7.2 UADS2.16 | length 245.6
  Layer 1 - Top Layer w10: UADS2.16@1904.84,1035.2 1904.84,970.16 1923.5,951.5 C121.1@1923.5,950
  Layer 1 - Top Layer w30: C121.1@1923.5,950 1923.5,886.5 C307.1@1930,880 L7.2@1930,800
NetC122_1: C122.1 C308.1 R261.1 UADS2.3 | length 247.2
  Layer 1 - Top Layer w10: UADS2.3@1904.84,1184.8 C122.1@1904.84,1285
  Layer 1 - Top Layer w30: C122.1@1913.5,1285 1913.5,1346.5 1905,1355 1913.5,1363.5 R261.1@1913.5,1425
NetC316_1: C316.1 FDA1.4 | length 104.3
  Layer 1 - Top Layer w8: C316.1@1390,2168.5 1423.5,2168.5 1444.88,2189.88 FDA1.4@1444.88,2230.47
NetC317_1: C317.1 FDA1.1 | length 104.3
  Layer 1 - Top Layer w8: C317.1@1390,2351.5 1423.5,2351.5 1444.88,2330.12 FDA1.1@1444.88,2289.53
NetC319_1: C319.1 R215.1 U4.1 | length 129.5
  Layer 1 - Top Layer w15: U4.1@1109.13,1742.86 1115,1736.99 1115,1689.13 C319.1@1121.5,1682.63 1183.5,1682.63 R215.1@1185,1684.13
NetC319_2: C319.2 R216.1 U4.4 | length 235.2
  Layer 1 - Top Layer w15: U4.4@1000.87,1817.66 1037.28,1817.66 1058.5,1796.44 C319.2@1058.5,1682.63 R216.1@1058.5,1627.63
NetC321_1: C321.1 R217.2 R218.1 TP28.1 U4.3 | length 276.7
  Layer 1 - Top Layer w15: U4.3@1109.13,1817.66 1137.4,1817.66 1148.87,1829.13 C321.1@1185,1829.13 R217.2@1240,1829.13 ; TP28.1@1240,1915.26 R217.2@1240,1829.13 ; R218.1@1295,1829.13 R217.2@1240,1829.13
NetC322_2: C322.2 R268.2 | length 67.4
  Layer 1 - Top Layer w10: R268.2@1995,2491.5 2020,2491.5 C322.2@2050,2461.5
NetC323_2: C323.2 R269.2 | length 65.4
  Layer 1 - Top Layer w10: R269.2@1770,1336.5 1800,1336.5 C323.2@1825,1311.5
NetCff2_1: Cff2.1 Cout4.1 L18.1 Rfbt2.2 U23.7
NetCff3_1: Cff3.1 Cout5.1 Cout6.1 L19.1 Rfbt3.2 U5.7
NetCss2_1: Css2.1 U23.5 | length 82.9
  Layer 4 - Bottom Layer w30: U23.5@3540.39,3385 Css2.1@3623.27,3385
NetCss3_1: Css3.1 U5.5 | length 253.6
  Layer 4 - Bottom Layer w30: U5.5@1350.63,285 1495,285 1544.93,235.07 Css3.1@1583.5,235.07
NetCss_2: Css.2 U22.5 | length 157.7
  Layer 4 - Bottom Layer w25: 1520.63,3300 Css.2@1678.35,3300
